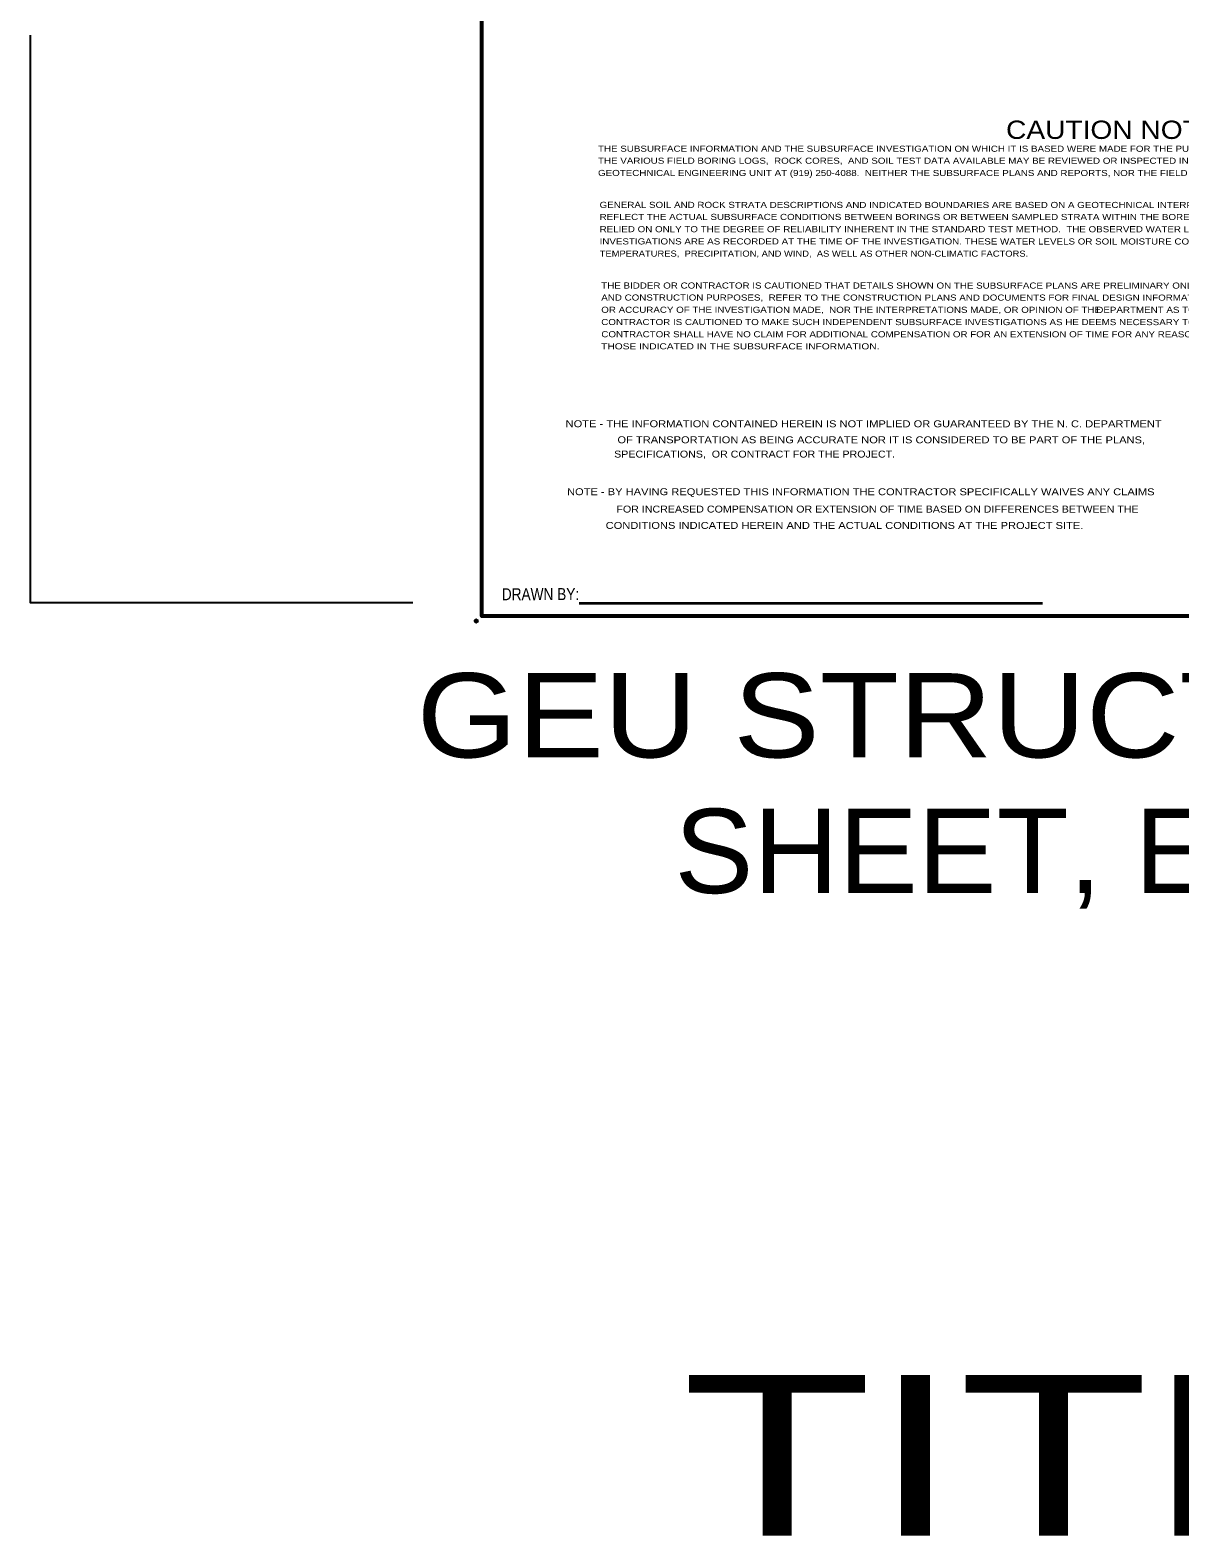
# Model space of a CAD drawing. Extents: x 278712 to 279914, y 171254 to 171792.
# Drawn here: x 278727.9 to 278799.6, y 171614.3 to 171708.2 of the extents above; entities that cross this region are included whole.
import ezdxf
from ezdxf.enums import TextEntityAlignment as Align

# ---------------------------------------------------------------- set-up
doc = ezdxf.new("R2010")
doc.units = 0
doc.header["$LTSCALE"] = 0.34
doc.header["$PDMODE"] = 32
doc.header["$PDSIZE"] = 0.17
doc.layers.add('60', color=7, linetype='Continuous', lineweight=35)
doc.layers.add('62', color=7, linetype='Continuous', lineweight=35)

msp = doc.modelspace()

# ---------------------------------------------------------------- linework, layer by layer
at = {"layer": '60'}
msp.add_line((278762.1524, 171672.527), (278791.0274, 171672.527), dxfattribs=at)
at = {"layer": '60', "lineweight": 53}
msp.add_lwpolyline([(278756.0874, 171774.8725), (278833.4716, 171774.8725), (278833.4716, 171671.7172), (278756.0874, 171671.7172)], close=True, dxfattribs=at)
at = {"layer": '60', "lineweight": 25}
msp.add_lwpolyline([(278727.9286, 171707.9072), (278727.9286, 171672.5682), (278751.7901, 171672.5682)], dxfattribs=at)
at = {"layer": '60'}
msp.add_point((278755.7374, 171671.4122), dxfattribs=at)

# ---------------------------------------------------------------- texts
for s, height, rotation, width, p in [('CAUTION NOTICE ', 1.14, 359.992, 1.15, (278788.7539, 171701.4425)), ('THE SUBSURFACE INFORMATION AND THE SUBSURFACE INVESTIGATION ON WHICH IT IS BASED WERE MADE FOR THE PURPOSE OF STUDY, PLANNING, AND DESIGN, AND NOT FOR CONSTRUCTION OR PAY PURPOSES. ', 0.3798, 359.992, 1.2, (278763.3226, 171700.6442)), ('THE VARIOUS FIELD BORING LOGS,  ROCK CORES,  AND SOIL TEST DATA AVAILABLE MAY BE REVIEWED OR INSPECTED IN RALEIGH BY CONTACTING THE N. C. DEPARTMENT OF TRANSPORTATION, ', 0.3798, 359.992, 1.2, (278763.3226, 171699.8955)), ('GEOTECHNICAL ENGINEERING UNIT AT (919) 250-4088.  NEITHER THE SUBSURFACE PLANS AND REPORTS, NOR THE FIELD BORING LOGS,  ROCK CORES,  OR SOIL TEST DATA ARE PART OF THE CONTRACT.', 0.3798, 359.992, 1.2, (278763.3226, 171699.1325)), ('GENERAL SOIL AND ROCK STRATA DESCRIPTIONS AND INDICATED BOUNDARIES ARE BASED ON A GEOTECHNICAL INTERPRETATION OF ALL AVAILABLE  SUBSURFACE DATA AND MAY NOT NECESSARILY', 0.3798, 359.992, 1.2, (278763.4214, 171697.1437)), ('REFLECT THE ACTUAL SUBSURFACE CONDITIONS BETWEEN BORINGS OR BETWEEN SAMPLED STRATA WITHIN THE BOREHOLE. THE LABORATORY SAMPLE DATA AND THE IN SITU (IN-PLACE) TEST DATA CAN BE', 0.3798, 359.992, 1.2, (278763.4214, 171696.3947)), ('RELIED ON ONLY TO THE DEGREE OF RELIABILITY INHERENT IN THE STANDARD TEST METHOD.  THE OBSERVED WATER LEVELS OR SOIL MOISTURE CONDITIONS INDICATED IN THE SUBSURFACE', 0.3798, 359.992, 1.2, (278763.4214, 171695.6317)), ('INVESTIGATIONS ARE AS RECORDED AT THE TIME OF THE INVESTIGATION. THESE WATER LEVELS OR SOIL MOISTURE CONDITIONS MAY VARY CONSIDERABLY WITH TIME ACCORDING TO CLIMATIC CONDITIONS INCLUDING', 0.3798, 359.992, 1.2, (278763.4214, 171694.868)), ('TEMPERATURES,  PRECIPITATION, AND WIND,  AS WELL AS OTHER NON-CLIMATIC FACTORS.', 0.3798, 359.992, 1.15, (278763.4266, 171694.1095)), ('THE BIDDER OR CONTRACTOR IS CAUTIONED THAT DETAILS SHOWN ON THE SUBSURFACE PLANS ARE PRELIMINARY ONLY AND IN MANY CASES THE FINAL DESIGN DETAILS ARE DIFFERENT.  FOR BIDDING', 0.3798, 359.992, 1.2, (278763.5251, 171692.1205)), ('AND CONSTRUCTION PURPOSES,  REFER TO THE CONSTRUCTION PLANS AND DOCUMENTS FOR FINAL DESIGN INFORMATION ON THIS PROJECT.  THE DEPARTMENT DOES NOT WARRANT OR GUARANTEE THE SUFFICIENCY', 0.3798, 359.992, 1.2, (278763.5251, 171691.3717)), ('OR ACCURACY OF THE INVESTIGATION MADE,  NOR THE INTERPRETATIONS MADE, OR OPINION OF THE ', 0.3793, 359.992, 1.2, (278763.5251, 171690.609)), ('CONTRACTOR IS CAUTIONED TO MAKE SUCH INDEPENDENT SUBSURFACE INVESTIGATIONS AS HE DEEMS NECESSARY TO SATISFY HIMSELF AS TO CONDITIONS TO BE ENCOUNTERED ON THIS PROJECT.  THE', 0.3798, 359.992, 1.2, (278763.5251, 171689.845)), ('DEPARTMENT AS TO THE TYPE OF MATERIALS AND CONDITIONS TO BE ENCOUNTERED.  THE BIDDER OR', 0.3798, 359.992, 1.2, (278794.3791, 171690.6045)), ('CONTRACTOR SHALL HAVE NO CLAIM FOR ADDITIONAL COMPENSATION OR FOR AN EXTENSION OF TIME FOR ANY REASON RESULTING FROM THE ACTUAL CONDITIONS ENCOUNTERED AT THE SITE DIFFERING FROM ', 0.3798, 359.992, 1.2, (278763.5304, 171689.0862)), ('THOSE INDICATED IN THE SUBSURFACE INFORMATION.', 0.3796, 359.992, 1.25, (278763.5206, 171688.3332)), ('DRAWN BY:', 0.7488, 0.132, 0.85, (278757.3264, 171672.703))]:
    msp.add_text(s, height=height, rotation=rotation, dxfattribs=dict(at, width=width)).set_placement(p)
for s, width, p in [('NOTE - THE INFORMATION CONTAINED HEREIN IS NOT IMPLIED OR GUARANTEED BY THE N. C. DEPARTMENT', 1.2, (278779.8781, 171683.4798)), ('OF TRANSPORTATION AS BEING ACCURATE NOR IT IS CONSIDERED TO BE PART OF THE PLANS,  ', 1.2, (278781.168, 171682.481)), ('SPECIFICATIONS,  OR CONTRACT FOR THE PROJECT.', 1.15, (278773.0842, 171681.5922)), ('NOTE - BY HAVING REQUESTED THIS INFORMATION THE CONTRACTOR SPECIFICALLY WAIVES ANY CLAIMS', 1.2, (278779.6991, 171679.246)), ('FOR INCREASED COMPENSATION OR EXTENSION OF TIME BASED ON DIFFERENCES BETWEEN THE', 1.15, (278780.7428, 171678.1643)), ('CONDITIONS INDICATED HEREIN AND THE ACTUAL CONDITIONS AT THE PROJECT SITE.', 1.2, (278778.684, 171677.1476))]:
    msp.add_text(s, height=0.4314, rotation=359.992, dxfattribs=dict(at, width=width)).set_placement(p, align=Align.CENTER)
for s, width, p in [('GEU STRUCTURE TITLE', 1.15, (278798.8925, 171662.911)), ('SHEET, ENGLISH', 1.05, (278798.603, 171654.461))]:
    msp.add_text(s, height=5.25, dxfattribs=dict(at, width=width)).set_placement(p, align=Align.CENTER)
at = {"layer": '62', "width": 1.45}
msp.add_text('TITLE SHEET: 11" x 17"', height=10, dxfattribs=at).set_placement((278768.5664, 171614.437))

doc.saveas('drawing.dxf')
